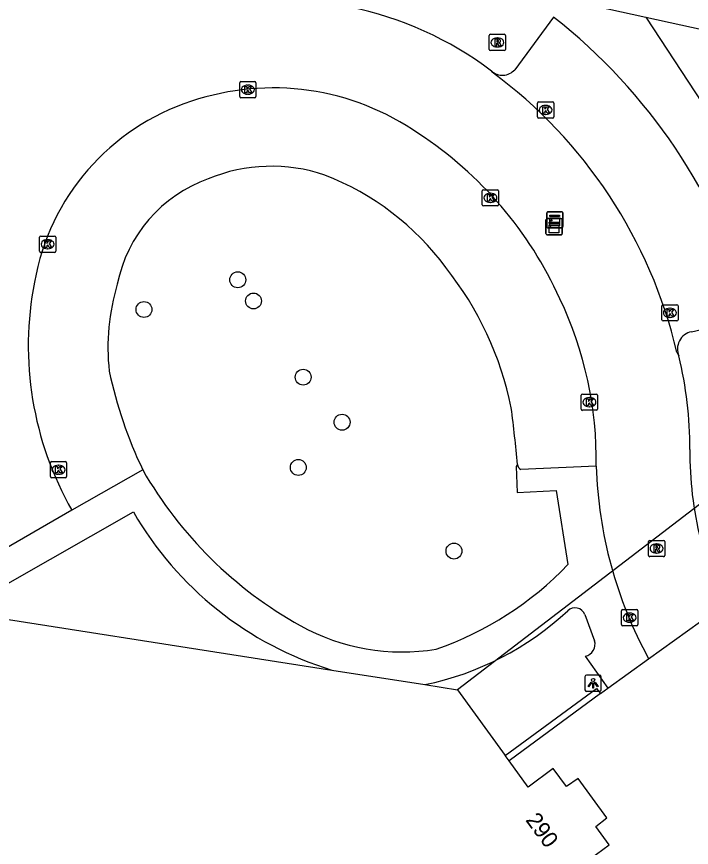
# Model space of a CAD drawing. Extents: x 161094 to 161705, y 379509 to 380907.
# Drawn here: x 161616.1 to 161657.6, y 380776.9 to 380828 of the extents above; entities that cross this region are included whole.
import ezdxf

# ---------------------------------------------------------------- set-up
doc = ezdxf.new("R2010")
doc.units = 0
for name, color, linetype in [('IMGEO_Boom', 7, 'Continuous'), ('IMGEO_Hek', 7, 'Continuous'), ('IMGEO_Kast', 7, 'Continuous'), ('IMGEO_Kolk', 7, 'Continuous'), ('IMGEO_Lichtpunt', 7, 'Continuous'), ('IMGEO_Muur', 7, 'Continuous'), ('IMGEO_Pand', 7, 'Continuous'), ('IMGEO_Pand_nummerreeks', 7, 'Continuous'), ('IMGEO_Parkeervlak_open', 7, 'Continuous'), ('IMGEO_Rijbaan_lokaal_open', 7, 'Continuous'), ('IMGEO_Rioolput', 7, 'Continuous'), ('IMGEO_Voetpad_open', 7, 'Continuous')]:
    doc.layers.add(name, color=color, linetype=linetype)

msp = doc.modelspace()

# ---------------------------------------------------------------- linework, layer by layer
at = {"layer": 'IMGEO_Boom'}
for centre in [(161629.714, 380811.831), (161630.682, 380810.527), (161623.943, 380810.002), (161633.739, 380805.839), (161636.133, 380803.066), (161633.441, 380800.284), (161643.019, 380795.139)]:
    msp.add_circle(centre, 0.489, dxfattribs=at)
at = {"layer": 'IMGEO_Hek'}
msp.add_lwpolyline([(161654.834, 380827.99), (161661.758, 380817.431), (161658.737, 380798.467), (161643.246, 380786.601)], dxfattribs=at)
at = {"layer": 'IMGEO_Kast'}
for p, q in [((161648.728, 380815.095), (161648.728, 380815.936)), ((161648.728, 380815.936), (161648.728, 380815.095)), ((161648.803, 380816.02), (161649.644, 380816.02)), ((161649.644, 380816.02), (161648.803, 380816.02)), ((161649.728, 380815.945), (161649.728, 380815.104)), ((161649.728, 380815.104), (161649.728, 380815.945)), ((161648.681, 380814.669), (161648.681, 380815.51)), ((161648.681, 380815.51), (161648.681, 380814.669)), ((161648.756, 380815.594), (161649.597, 380815.594)), ((161649.597, 380815.594), (161648.756, 380815.594)), ((161649.681, 380815.519), (161649.681, 380814.678)), ((161649.681, 380814.678), (161649.681, 380815.519)), ((161649.653, 380815.02), (161648.812, 380815.02)), ((161648.812, 380815.02), (161649.653, 380815.02)), ((161649.606, 380814.594), (161648.765, 380814.594)), ((161648.765, 380814.594), (161649.606, 380814.594))]:
    msp.add_line(p, q, dxfattribs=at)
for points in [[(161648.923, 380815.81), (161649.523, 380815.81), (161649.523, 380815.725), (161648.923, 380815.725), (161648.923, 380815.81)], [(161648.876, 380815.384), (161649.476, 380815.384), (161649.476, 380815.299), (161648.876, 380815.299), (161648.876, 380815.384)], [(161648.923, 380815.635), (161649.523, 380815.635), (161649.523, 380815.146), (161648.923, 380815.146), (161648.923, 380815.635)], [(161648.876, 380815.209), (161649.476, 380815.209), (161649.476, 380814.72), (161648.876, 380814.72), (161648.876, 380815.209)]]:
    msp.add_lwpolyline(points, dxfattribs=at)
for centre in [(161649.007, 380815.484), (161648.96, 380815.058)]:
    msp.add_circle(centre, 0.0377, dxfattribs=at)
for centre, start, end in [((161648.806, 380815.942), 92.4484, 184.2845), ((161648.806, 380815.942), 92.4484, 184.2845), ((161649.65, 380815.942), 2.4484, 94.2845), ((161649.65, 380815.942), 2.4484, 94.2845), ((161648.759, 380815.516), 92.4484, 184.2845), ((161648.759, 380815.516), 92.4484, 184.2845), ((161649.603, 380815.516), 2.4484, 94.2845), ((161649.603, 380815.516), 2.4484, 94.2845), ((161648.806, 380815.098), 182.4484, 274.2845), ((161648.806, 380815.098), 182.4484, 274.2845), ((161649.65, 380815.098), 272.4484, 4.2845), ((161649.65, 380815.098), 272.4484, 4.2845), ((161648.759, 380814.672), 182.4484, 274.2845), ((161648.759, 380814.672), 182.4484, 274.2845), ((161649.603, 380814.672), 272.4484, 4.2845), ((161649.603, 380814.672), 272.4484, 4.2845)]:
    msp.add_arc(centre, 0.0779, start, end, dxfattribs=at)
at = {"layer": 'IMGEO_Kolk'}
for p, q in [((161629.835, 380823.105), (161629.835, 380823.957)), ((161629.91, 380824.031), (161630.762, 380824.031)), ((161630.836, 380823.957), (161630.836, 380823.105)), ((161630.323, 380823.811), (161630.348, 380823.811)), ((161630.762, 380823.031), (161629.91, 380823.031)), ((161630.346, 380823.251), (161630.321, 380823.251)), ((161648.16, 380821.856), (161648.16, 380822.708)), ((161648.235, 380822.782), (161649.087, 380822.782)), ((161648.648, 380822.562), (161648.673, 380822.562)), ((161649.161, 380822.708), (161649.161, 380821.856)), ((161648.671, 380822.002), (161648.646, 380822.002)), ((161649.087, 380821.782), (161648.235, 380821.782)), ((161644.761, 380816.447), (161644.761, 380817.299)), ((161644.836, 380817.373), (161645.688, 380817.373)), ((161645.762, 380817.299), (161645.762, 380816.447)), ((161645.249, 380817.153), (161645.274, 380817.153)), ((161645.688, 380816.373), (161644.836, 380816.373)), ((161645.272, 380816.593), (161645.247, 380816.593)), ((161617.515, 380813.593), (161617.515, 380814.445)), ((161617.59, 380814.519), (161618.442, 380814.519)), ((161618.003, 380814.299), (161618.028, 380814.299)), ((161618.516, 380814.445), (161618.516, 380813.593)), ((161618.026, 380813.739), (161618.001, 380813.739)), ((161618.442, 380813.519), (161617.59, 380813.519)), ((161655.808, 380809.373), (161655.808, 380810.225)), ((161655.883, 380810.299), (161656.735, 380810.299)), ((161656.809, 380810.225), (161656.809, 380809.373)), ((161656.296, 380810.079), (161656.321, 380810.079)), ((161656.735, 380809.299), (161655.883, 380809.299)), ((161656.319, 380809.519), (161656.294, 380809.519)), ((161650.854, 380803.872), (161650.854, 380804.724)), ((161650.929, 380804.798), (161651.781, 380804.798)), ((161651.342, 380804.578), (161651.367, 380804.578)), ((161651.855, 380804.724), (161651.855, 380803.872)), ((161651.365, 380804.018), (161651.34, 380804.018)), ((161651.781, 380803.798), (161650.929, 380803.798)), ((161618.183, 380799.717), (161618.183, 380800.569)), ((161618.258, 380800.643), (161619.11, 380800.643)), ((161619.184, 380800.569), (161619.184, 380799.717)), ((161618.671, 380800.423), (161618.696, 380800.423)), ((161619.11, 380799.643), (161618.258, 380799.643)), ((161618.694, 380799.863), (161618.669, 380799.863)), ((161653.33, 380790.616), (161653.33, 380791.468)), ((161653.405, 380791.542), (161654.257, 380791.542)), ((161653.818, 380791.322), (161653.843, 380791.322)), ((161654.331, 380791.468), (161654.331, 380790.616)), ((161653.841, 380790.762), (161653.816, 380790.762)), ((161654.257, 380790.542), (161653.405, 380790.542))]:
    msp.add_line(p, q, dxfattribs=at)
for points in [[(161629.835, 380823.105), (161629.835, 380823.957)], [(161629.91, 380824.031), (161630.762, 380824.031)], [(161630.836, 380823.957), (161630.836, 380823.105)], [(161630.156, 380823.731), (161630.279, 380823.731), (161630.279, 380823.58), (161630.409, 380823.731), (161630.573, 380823.731), (161630.427, 380823.58), (161630.58, 380823.331), (161630.428, 380823.331), (161630.343, 380823.495), (161630.279, 380823.428), (161630.279, 380823.331), (161630.156, 380823.331), (161630.156, 380823.731)], [(161630.762, 380823.031), (161629.91, 380823.031)], [(161648.16, 380821.856), (161648.16, 380822.708)], [(161648.235, 380822.782), (161649.087, 380822.782)], [(161648.481, 380822.482), (161648.604, 380822.482), (161648.604, 380822.331), (161648.734, 380822.482), (161648.898, 380822.482), (161648.752, 380822.331), (161648.905, 380822.082), (161648.753, 380822.082), (161648.668, 380822.246), (161648.604, 380822.179), (161648.604, 380822.082), (161648.481, 380822.082), (161648.481, 380822.482)], [(161649.161, 380822.708), (161649.161, 380821.856)], [(161649.087, 380821.782), (161648.235, 380821.782)], [(161644.761, 380816.447), (161644.761, 380817.299)], [(161644.836, 380817.373), (161645.688, 380817.373)], [(161645.762, 380817.299), (161645.762, 380816.447)], [(161645.082, 380817.073), (161645.205, 380817.073), (161645.205, 380816.922), (161645.335, 380817.073), (161645.499, 380817.073), (161645.353, 380816.922), (161645.506, 380816.673), (161645.354, 380816.673), (161645.269, 380816.837), (161645.205, 380816.77), (161645.205, 380816.673), (161645.082, 380816.673), (161645.082, 380817.073)], [(161645.688, 380816.373), (161644.836, 380816.373)], [(161617.515, 380813.593), (161617.515, 380814.445)], [(161617.59, 380814.519), (161618.442, 380814.519)], [(161618.516, 380814.445), (161618.516, 380813.593)], [(161617.836, 380814.219), (161617.959, 380814.219), (161617.959, 380814.068), (161618.089, 380814.219), (161618.253, 380814.219), (161618.107, 380814.068), (161618.26, 380813.819), (161618.108, 380813.819), (161618.023, 380813.983), (161617.959, 380813.916), (161617.959, 380813.819), (161617.836, 380813.819), (161617.836, 380814.219)], [(161618.442, 380813.519), (161617.59, 380813.519)], [(161655.808, 380809.373), (161655.808, 380810.225)], [(161655.883, 380810.299), (161656.735, 380810.299)], [(161656.809, 380810.225), (161656.809, 380809.373)], [(161656.129, 380809.999), (161656.252, 380809.999), (161656.252, 380809.848), (161656.382, 380809.999), (161656.546, 380809.999), (161656.4, 380809.848), (161656.553, 380809.599), (161656.401, 380809.599), (161656.316, 380809.763), (161656.252, 380809.696), (161656.252, 380809.599), (161656.129, 380809.599), (161656.129, 380809.999)], [(161656.735, 380809.299), (161655.883, 380809.299)], [(161650.854, 380803.872), (161650.854, 380804.724)], [(161650.929, 380804.798), (161651.781, 380804.798)], [(161651.855, 380804.724), (161651.855, 380803.872)], [(161651.175, 380804.498), (161651.298, 380804.498), (161651.298, 380804.347), (161651.428, 380804.498), (161651.592, 380804.498), (161651.446, 380804.347), (161651.599, 380804.098), (161651.447, 380804.098), (161651.362, 380804.262), (161651.298, 380804.195), (161651.298, 380804.098), (161651.175, 380804.098), (161651.175, 380804.498)], [(161651.781, 380803.798), (161650.929, 380803.798)], [(161618.183, 380799.717), (161618.183, 380800.569)], [(161618.258, 380800.643), (161619.11, 380800.643)], [(161619.184, 380800.569), (161619.184, 380799.717)], [(161618.504, 380800.343), (161618.627, 380800.343), (161618.627, 380800.192), (161618.757, 380800.343), (161618.921, 380800.343), (161618.775, 380800.192), (161618.928, 380799.943), (161618.776, 380799.943), (161618.691, 380800.107), (161618.627, 380800.04), (161618.627, 380799.943), (161618.504, 380799.943), (161618.504, 380800.343)], [(161619.11, 380799.643), (161618.258, 380799.643)], [(161653.33, 380790.616), (161653.33, 380791.468)], [(161653.405, 380791.542), (161654.257, 380791.542)], [(161653.651, 380791.242), (161653.774, 380791.242), (161653.774, 380791.091), (161653.904, 380791.242), (161654.068, 380791.242), (161653.922, 380791.091), (161654.075, 380790.842), (161653.923, 380790.842), (161653.838, 380791.006), (161653.774, 380790.939), (161653.774, 380790.842), (161653.651, 380790.842), (161653.651, 380791.242)], [(161654.331, 380791.468), (161654.331, 380790.616)], [(161654.257, 380790.542), (161653.405, 380790.542)]]:
    msp.add_lwpolyline(points, dxfattribs=at)
for centre, start, end in [((161629.912, 380823.955), 91.552, 178.448), ((161629.912, 380823.955), 91.552, 178.448), ((161630.76, 380823.955), 1.552, 88.448), ((161630.76, 380823.955), 1.552, 88.448), ((161629.912, 380823.107), 181.552, 268.448), ((161629.912, 380823.107), 181.552, 268.448), ((161630.76, 380823.107), 271.552, 358.448), ((161630.76, 380823.107), 271.552, 358.448), ((161648.237, 380822.706), 91.552, 178.448), ((161648.237, 380822.706), 91.552, 178.448), ((161649.085, 380822.706), 1.552, 88.448), ((161649.085, 380822.706), 1.552, 88.448), ((161648.237, 380821.858), 181.552, 268.448), ((161648.237, 380821.858), 181.552, 268.448), ((161649.085, 380821.858), 271.552, 358.448), ((161649.085, 380821.858), 271.552, 358.448), ((161644.838, 380817.297), 91.552, 178.448), ((161644.838, 380817.297), 91.552, 178.448), ((161645.686, 380817.297), 1.552, 88.448), ((161645.686, 380817.297), 1.552, 88.448), ((161644.838, 380816.449), 181.552, 268.448), ((161644.838, 380816.449), 181.552, 268.448), ((161645.686, 380816.449), 271.552, 358.448), ((161645.686, 380816.449), 271.552, 358.448), ((161617.592, 380814.443), 91.552, 178.448), ((161617.592, 380814.443), 91.552, 178.448), ((161618.44, 380814.443), 1.552, 88.448), ((161618.44, 380814.443), 1.552, 88.448), ((161617.592, 380813.595), 181.552, 268.448), ((161617.592, 380813.595), 181.552, 268.448), ((161618.44, 380813.595), 271.552, 358.448), ((161618.44, 380813.595), 271.552, 358.448), ((161655.885, 380810.223), 91.552, 178.448), ((161655.885, 380810.223), 91.552, 178.448), ((161656.733, 380810.223), 1.552, 88.448), ((161656.733, 380810.223), 1.552, 88.448), ((161655.885, 380809.375), 181.552, 268.448), ((161655.885, 380809.375), 181.552, 268.448), ((161656.733, 380809.375), 271.552, 358.448), ((161656.733, 380809.375), 271.552, 358.448), ((161650.931, 380804.722), 91.552, 178.448), ((161650.931, 380804.722), 91.552, 178.448), ((161651.779, 380804.722), 1.552, 88.448), ((161651.779, 380804.722), 1.552, 88.448), ((161650.931, 380803.874), 181.552, 268.448), ((161650.931, 380803.874), 181.552, 268.448), ((161651.779, 380803.874), 271.552, 358.448), ((161651.779, 380803.874), 271.552, 358.448), ((161618.26, 380800.567), 91.552, 178.448), ((161618.26, 380800.567), 91.552, 178.448), ((161619.108, 380800.567), 1.552, 88.448), ((161619.108, 380800.567), 1.552, 88.448), ((161618.26, 380799.719), 181.552, 268.448), ((161618.26, 380799.719), 181.552, 268.448), ((161619.108, 380799.719), 271.552, 358.448), ((161619.108, 380799.719), 271.552, 358.448), ((161653.407, 380791.466), 91.552, 178.448), ((161653.407, 380791.466), 91.552, 178.448), ((161654.255, 380791.466), 1.552, 88.448), ((161654.255, 380791.466), 1.552, 88.448), ((161653.407, 380790.618), 181.552, 268.448), ((161653.407, 380790.618), 181.552, 268.448), ((161654.255, 380790.618), 271.552, 358.448), ((161654.255, 380790.618), 271.552, 358.448)]:
    msp.add_arc(centre, 0.0765, start, end, dxfattribs=at)
for centre, major_axis, ratio, start_param, end_param in [((161630.322, 380823.531), (-0.387, 0.002), 0.722429, 4.712389, 7.853982), ((161630.347, 380823.531), (-0.39, 0.002), 0.717154, 1.570796, 4.712389), ((161648.647, 380822.282), (-0.387, 0.002), 0.722429, 4.712389, 7.853982), ((161648.672, 380822.282), (-0.39, 0.002), 0.717154, 1.570796, 4.712389), ((161645.248, 380816.873), (-0.387, 0.002), 0.722429, 4.712389, 7.853982), ((161645.273, 380816.873), (-0.39, 0.002), 0.717154, 1.570796, 4.712389), ((161618.002, 380814.019), (-0.387, 0.002), 0.722429, 4.712389, 7.853982), ((161618.027, 380814.019), (-0.39, 0.002), 0.717154, 1.570796, 4.712389), ((161656.295, 380809.799), (-0.387, 0.002), 0.722429, 4.712389, 7.853982), ((161656.32, 380809.799), (-0.39, 0.002), 0.717154, 1.570796, 4.712389), ((161651.341, 380804.298), (-0.387, 0.002), 0.722429, 4.712389, 7.853982), ((161651.366, 380804.298), (-0.39, 0.002), 0.717154, 1.570796, 4.712389), ((161618.67, 380800.143), (-0.387, 0.002), 0.722429, 4.712389, 7.853982), ((161618.695, 380800.143), (-0.39, 0.002), 0.717154, 1.570796, 4.712389), ((161653.817, 380791.042), (-0.387, 0.002), 0.722429, 4.712389, 7.853982), ((161653.842, 380791.042), (-0.39, 0.002), 0.717154, 1.570796, 4.712389)]:
    msp.add_ellipse(centre, major_axis=major_axis, ratio=ratio, start_param=start_param, end_param=end_param, dxfattribs=at)
at = {"layer": 'IMGEO_Lichtpunt'}
for p, q in [((161651.081, 380787.409), (161651.081, 380786.602)), ((161651.081, 380787.409), (161651.081, 380786.602)), ((161651.983, 380787.504), (161651.175, 380787.504)), ((161651.983, 380787.504), (161651.175, 380787.504)), ((161652.077, 380786.602), (161652.077, 380787.409)), ((161652.077, 380786.602), (161652.077, 380787.409)), ((161651.175, 380786.508), (161651.983, 380786.508)), ((161651.175, 380786.508), (161651.983, 380786.508))]:
    msp.add_line(p, q, dxfattribs=at)
for points in [[(161651.455, 380787.073), (161651.494, 380787.045), (161651.306, 380786.783), (161651.268, 380786.81), (161651.455, 380787.073)], [(161651.557, 380787.025), (161651.604, 380787.025), (161651.604, 380786.703), (161651.557, 380786.703), (161651.557, 380787.025)], [(161651.667, 380787.045), (161651.705, 380787.072), (161651.892, 380786.81), (161651.853, 380786.782), (161651.667, 380787.045)]]:
    msp.add_lwpolyline(points, dxfattribs=at)
msp.add_circle((161651.58, 380787.207), 0.0994, dxfattribs=at)
for centre, start, end in [((161651.175, 380787.409), 90, 180), ((161651.175, 380787.409), 90, 180), ((161651.983, 380787.409), 0, 90), ((161651.983, 380787.409), 0, 90), ((161651.175, 380786.602), 180, 270), ((161651.175, 380786.602), 180, 270), ((161651.983, 380786.602), 270, 0), ((161651.983, 380786.602), 270, 360)]:
    msp.add_arc(centre, 0.0946, start, end, dxfattribs=at)
at = {"layer": 'IMGEO_Muur'}
for points in [[(161646.179, 380782.556), (161651.79, 380786.687), (161652.028, 380786.369)], [(161652.028, 380786.369), (161646.411, 380782.235)]]:
    msp.add_lwpolyline(points, dxfattribs=at)
at = {"layer": 'IMGEO_Pand'}
for points in [[(161609.033, 380791.958), (161635.512, 380787.812)], [(161635.512, 380787.812), (161641.217, 380786.919)], [(161641.217, 380786.919), (161643.246, 380786.601), (161646.179, 380782.556)], [(161646.411, 380782.235), (161646.179, 380782.556)], [(161652.167, 380774.32), (161651.017, 380775.909), (161652.573, 380777.061), (161651.743, 380778.194), (161652.429, 380778.714), (161650.668, 380781.143), (161649.954, 380780.648), (161649.119, 380781.768), (161647.581, 380780.621), (161646.411, 380782.235)]]:
    msp.add_lwpolyline(points, dxfattribs=at)
at = {"layer": 'IMGEO_Parkeervlak_open'}
for points in [[(161649.152, 380827.988), (161646.757, 380824.756)], [(161657.629, 380808.636), (161660.974, 380809.412)]]:
    msp.add_lwpolyline(points, dxfattribs=at)
for centre, radius, start, end in [((161627.596, 380800.454), 34.969, 15.7354, 51.9431), ((161646.003, 380825.422), 1.006, 227.7656, 318.5586), ((161631.786, 380808.629), 10.187, 71.2087, 112.4051), ((161630.835, 380809.85), 8.706, 109.6822, 168.6628), ((161629.03, 380802.636), 16.762, 36.3792, 68.8894), ((161626.422, 380799.822), 20.543, 11.5768, 38.3836), ((161635.4, 380807.644), 13.674, 163.3551, 186.0419), ((161657.87, 380807.565), 1.098, 102.6671, 202.4324), ((161648.936, 380812.052), 27.757, 192.1606, 205.4324), ((161531.216, 380789.405), 116.244, 5.46247, 7.18533)]:
    msp.add_arc(centre, radius, start, end, dxfattribs=at)
at = {"layer": 'IMGEO_Rijbaan_lokaal_open'}
for points in [[(161645.327, 380824.677), (161645.375, 380824.604)], [(161656.734, 380807.378), (161656.855, 380807.146)], [(161619.511, 380797.645), (161614.553, 380794.801)], [(161655, 380788.512), (161659.78, 380791.959)], [(161652.485, 380786.699), (161655, 380788.512)], [(161652.028, 380786.369), (161652.485, 380786.699)]]:
    msp.add_lwpolyline(points, dxfattribs=at)
for centre, radius, start, end in [((161632.331, 380807.47), 21.563, 52.9366, 78.5456), ((161627.548, 380800.49), 29.988, 13.2782, 53.5244), ((161631.879, 380807.958), 15.68, 55.0644, 108.6753), ((161631.274, 380809.232), 14.279, 108.0129, 170.0736), ((161627.761, 380800.826), 23.895, 24.3182, 56.7634), ((161637.192, 380807.757), 20.368, 168.8541, 209.7649), ((161628.723, 380800.753), 23.053, 359.0242, 25.4689), ((161634.004, 380801.536), 23.529, 359.6267, 13.793), ((161679.699, 380801.203), 22.167, 179.5342, 193.9816), ((161678.08, 380801.162), 26.319, 181.7456, 208.7261)]:
    msp.add_arc(centre, radius, start, end, dxfattribs=at)
at = {"layer": 'IMGEO_Rioolput'}
for p, q in [((161645.188, 380826.008), (161645.188, 380826.86)), ((161645.263, 380826.934), (161646.115, 380826.934)), ((161645.676, 380826.714), (161645.701, 380826.714)), ((161646.189, 380826.86), (161646.189, 380826.008)), ((161645.699, 380826.154), (161645.674, 380826.154)), ((161646.115, 380825.934), (161645.263, 380825.934)), ((161654.988, 380794.868), (161654.988, 380795.72)), ((161655.063, 380795.794), (161655.915, 380795.794)), ((161655.476, 380795.574), (161655.501, 380795.574)), ((161655.989, 380795.72), (161655.989, 380794.868)), ((161655.499, 380795.014), (161655.474, 380795.014)), ((161655.915, 380794.794), (161655.063, 380794.794))]:
    msp.add_line(p, q, dxfattribs=at)
for points in [[(161645.188, 380826.008), (161645.188, 380826.86)], [(161645.263, 380826.934), (161646.115, 380826.934)], [(161645.777, 380826.632), (161645.525, 380826.634), (161645.525, 380826.234)], [(161645.703, 380826.553), (161645.649, 380826.553), (161645.649, 380826.472)], [(161646.189, 380826.86), (161646.189, 380826.008)], [(161645.525, 380826.234), (161645.649, 380826.234), (161645.649, 380826.396), (161645.66, 380826.396)], [(161645.649, 380826.472), (161645.701, 380826.472)], [(161645.707, 380826.367), (161645.778, 380826.234), (161645.918, 380826.234), (161645.853, 380826.36)], [(161646.115, 380825.934), (161645.263, 380825.934)], [(161654.988, 380794.868), (161654.988, 380795.72)], [(161655.063, 380795.794), (161655.915, 380795.794)], [(161655.577, 380795.492), (161655.325, 380795.494), (161655.325, 380795.094)], [(161655.503, 380795.413), (161655.449, 380795.413), (161655.449, 380795.332)], [(161655.449, 380795.332), (161655.501, 380795.332)], [(161655.989, 380795.72), (161655.989, 380794.868)], [(161655.325, 380795.094), (161655.449, 380795.094), (161655.449, 380795.256), (161655.46, 380795.256)], [(161655.507, 380795.227), (161655.578, 380795.094), (161655.718, 380795.094), (161655.653, 380795.22)], [(161655.915, 380794.794), (161655.063, 380794.794)]]:
    msp.add_lwpolyline(points, dxfattribs=at)
for centre, radius, start, end in [((161645.265, 380826.858), 0.0765, 91.552, 178.448), ((161645.265, 380826.858), 0.0765, 91.552, 178.448), ((161645.709, 380826.457), 0.0964, 77.0061, 93.1865), ((161645.723, 380826.514), 0.0378, 276.6634, 79.6772), ((161645.776, 380826.522), 0.109, 350.3612, 89.416), ((161645.774, 380826.522), 0.112, 277.5842, 350.9817), ((161646.113, 380826.858), 0.0765, 1.552, 88.448), ((161646.113, 380826.858), 0.0765, 1.552, 88.448), ((161645.265, 380826.01), 0.0765, 181.552, 268.448), ((161645.265, 380826.01), 0.0765, 181.552, 268.448), ((161645.659, 380826.343), 0.0533, 26.0293, 88.6989), ((161645.685, 380826.661), 0.19, 274.7715, 282.9687), ((161645.758, 380826.307), 0.108, 29.5134, 73.7905), ((161646.113, 380826.01), 0.0765, 271.552, 358.448), ((161646.113, 380826.01), 0.0765, 271.552, 358.448), ((161655.065, 380795.718), 0.0765, 91.552, 178.448), ((161655.065, 380795.718), 0.0765, 91.552, 178.448), ((161655.485, 380795.521), 0.19, 274.7715, 282.9687), ((161655.509, 380795.317), 0.0964, 77.0061, 93.1865), ((161655.523, 380795.374), 0.0378, 276.6634, 79.6772), ((161655.576, 380795.382), 0.109, 350.3612, 89.416), ((161655.574, 380795.382), 0.112, 277.5842, 350.9817), ((161655.913, 380795.718), 0.0765, 1.552, 88.448), ((161655.913, 380795.718), 0.0765, 1.552, 88.448), ((161655.065, 380794.87), 0.0765, 181.552, 268.448), ((161655.065, 380794.87), 0.0765, 181.552, 268.448), ((161655.459, 380795.203), 0.0533, 26.0293, 88.6989), ((161655.558, 380795.167), 0.108, 29.5134, 73.7905), ((161655.913, 380794.87), 0.0765, 271.552, 358.448), ((161655.913, 380794.87), 0.0765, 271.552, 358.448)]:
    msp.add_arc(centre, radius, start, end, dxfattribs=at)
for centre, major_axis, ratio, start_param, end_param in [((161645.675, 380826.434), (-0.387, 0.002), 0.722429, 4.712389, 7.853982), ((161645.7, 380826.434), (-0.39, 0.002), 0.717154, 1.570796, 4.712389), ((161655.475, 380795.294), (-0.387, 0.002), 0.722429, 4.712389, 7.853982), ((161655.5, 380795.294), (-0.39, 0.002), 0.717154, 1.570796, 4.712389)]:
    msp.add_ellipse(centre, major_axis=major_axis, ratio=ratio, start_param=start_param, end_param=end_param, dxfattribs=at)
at = {"layer": 'IMGEO_Voetpad_open'}
for points in [[(161603.174, 380837.856), (161633.826, 380832.562), (161635.924, 380832.159), (161654.834, 380827.99), (161667.085, 380825.298)], [(161646.932, 380800.471), (161646.844, 380800.346), (161646.908, 380798.742), (161649.313, 380798.869), (161650.034, 380794.315)], [(161623.869, 380800.132), (161619.511, 380797.645)], [(161651.773, 380800.36), (161647.138, 380800.166)], [(161614.553, 380794.801), (161615.567, 380793.137), (161623.296, 380797.544)], [(161651.068, 380791.23), (161651.672, 380789.625)], [(161651.098, 380788.666), (161652.485, 380786.699)]]:
    msp.add_lwpolyline(points, dxfattribs=at)
for centre, radius, start, end in [((161647.26, 380800.47), 0.328, 179.855, 248.216), ((161645.871, 380812.709), 25.343, 209.7542, 240.9475), ((161641.747, 380808.172), 21.293, 209.9413, 252.9729), ((161635.3, 380808.346), 20.346, 289.0068, 316.4008), ((161637.556, 380804.791), 18.243, 281.5773, 313.0842), ((161650.465, 380791.004), 0.644, 20.5606, 134.0241), ((161639.804, 380801.739), 12.807, 240.8408, 279.5375), ((161650.929, 380789.419), 0.771, 282.6829, 15.5127)]:
    msp.add_arc(centre, radius, start, end, dxfattribs=at)

# ---------------------------------------------------------------- texts
at = {"layer": 'IMGEO_Pand_nummerreeks'}
msp.add_text('290', height=1, rotation=306.2737, dxfattribs=at).set_placement((161647.388, 380778.583))

doc.saveas('drawing.dxf')
